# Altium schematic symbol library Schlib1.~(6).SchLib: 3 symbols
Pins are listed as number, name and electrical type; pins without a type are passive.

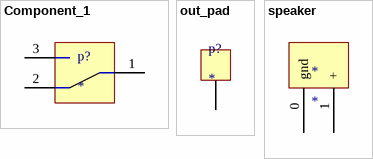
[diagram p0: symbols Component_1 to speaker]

## Component_1
designator p?
pins: 1 in, 2, 3

## out_pad
designator p?
footprint pad
pins: 0

## speaker
designator *
footprint speaker
pins: 0 gnd, 1 +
